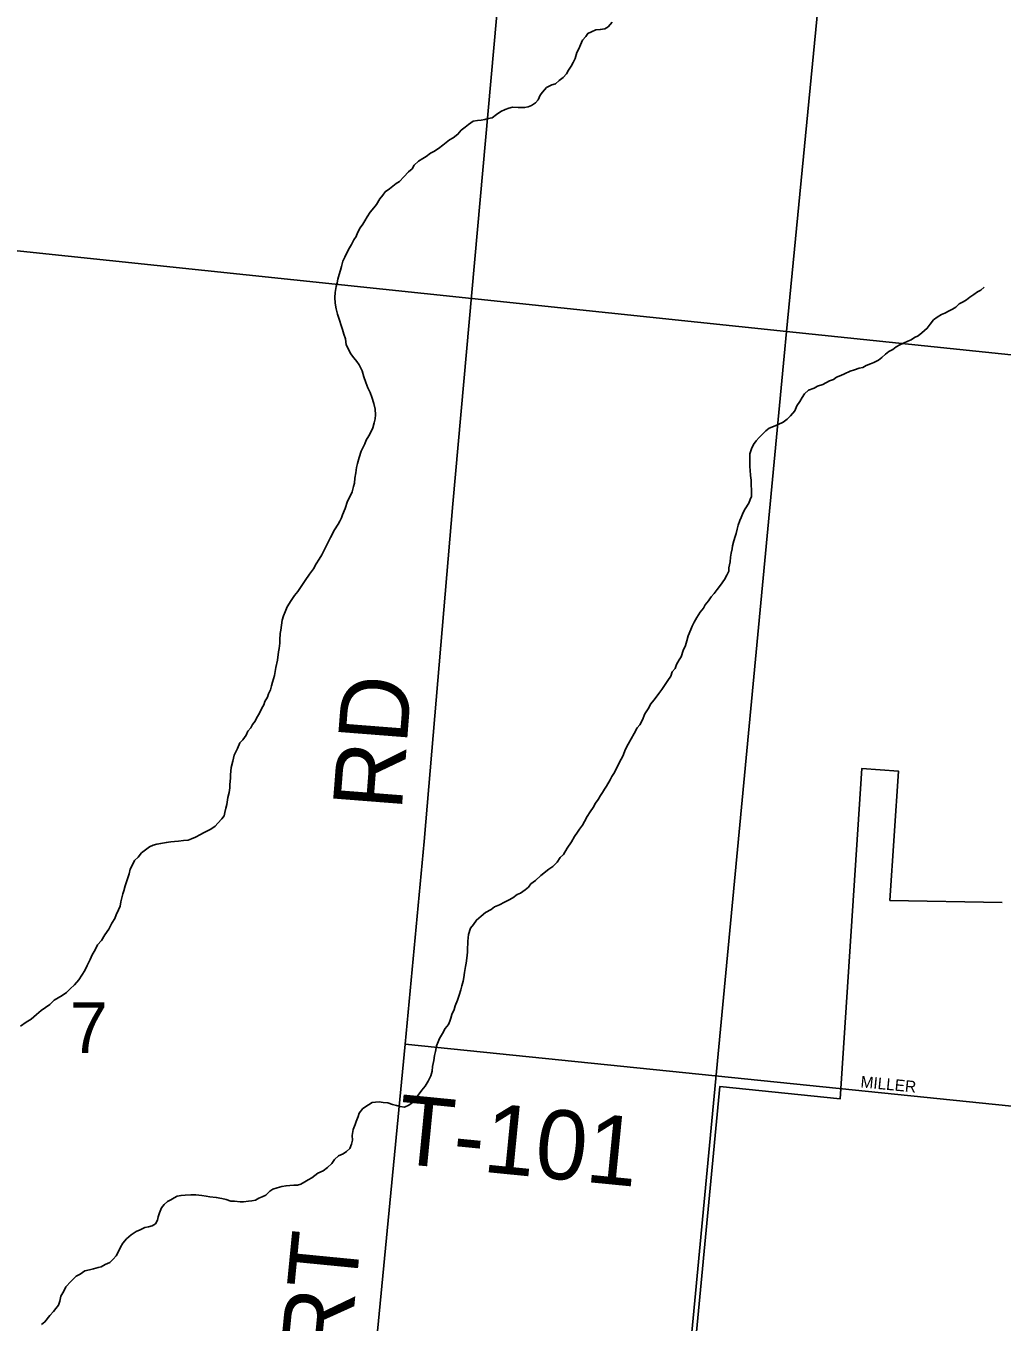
# Model space of a CAD drawing. Extents: x 1310247 to 1664935, y 284496 to 704931.
# Drawn here: x 1478998 to 1483233, y 534778 to 540403 of the extents above; entities that cross this region are included whole.
import ezdxf

# ---------------------------------------------------------------- set-up
doc = ezdxf.new("R2010")
doc.units = 0
for name, color, linetype in [('GM_X_Corporation_Text', 7, 'Continuous'), ('GM_X_County', 7, 'Continuous'), ('GM_X_County_Road_Text', 7, 'Continuous'), ('GM_X_County_Subdivision_Text', 7, 'Continuous'), ('GM_X_Major_Lake_Text', 7, 'Continuous'), ('GM_X_Minor_River_Text', 7, 'Continuous'), ('GM_X_Rail_Line', 7, 'Continuous'), ('GM_X_Township_Road', 7, 'Continuous'), ('GM_X_Township_Subdivision', 7, 'Continuous'), ('GM_X_US_Location', 7, 'Continuous')]:
    doc.layers.add(name, color=color, linetype=linetype)

msp = doc.modelspace()

# ---------------------------------------------------------------- linework, layer by layer
at = {"layer": 'GM_X_Corporation_Text'}
msp.add_lwpolyline([(1482526.6, 535791.8), (1484192.7, 535621.9), (1484200.6, 535621.1)], dxfattribs=at)
at = {"layer": 'GM_X_County'}
for points in [[(1482824.4, 544500.5), (1482296.8, 539077.3), (1476836.6, 539649.6), (1477436.1, 545815.4)], [(1488278.4, 543814.4), (1487769.1, 538508.9), (1482296.8, 539077.3), (1482824.4, 544500.5)], [(1482296.8, 539077.3), (1481688, 532623.9), (1476536.2, 533008.3), (1476252.8, 533037.6), (1476836.6, 539649.6)], [(1487769.1, 538508.9), (1487146.6, 532073.7), (1481965.4, 532596.7), (1481688, 532623.9), (1482296.8, 539077.3)]]:
    msp.add_lwpolyline(points, close=True, dxfattribs=at)
at = {"layer": 'GM_X_County_Road_Text'}
msp.add_lwpolyline([(1481149, 532772.8), (1481084.4, 532843.1), (1480900.4, 533069.7), (1480812.9, 533208.1), (1480562.1, 533693.1), (1480490.5, 533821.1), (1480457.7, 533888), (1480449.5, 533974.5), (1480643.3, 535983.8), (1480726.5, 536863.2), (1480850.5, 538329.9), (1481180.6, 542015), (1481216.3, 542748.8), (1481232.1, 543112), (1481249.6, 543457.3), (1481303, 544311.9), (1481316.9, 544534.5), (1481345.5, 544835.1)], dxfattribs=at)
at = {"layer": 'GM_X_County_Subdivision_Text'}
msp.add_lwpolyline([(1480643.3, 535983.8), (1482526.6, 535791.8)], dxfattribs=at)
at = {"layer": 'GM_X_Major_Lake_Text'}
msp.add_lwpolyline([(1483665.3, 533123.9), (1482695.3, 533200.4), (1481767.3, 533260.9), (1482008, 535800.7), (1482530.4, 535747.7), (1482624.4, 537180.8), (1482782.6, 537169.7), (1482746.2, 536608.1), (1483233.2, 536598.6)], dxfattribs=at)
at = {"layer": 'GM_X_Minor_River_Text'}
for points in [[(1481092.9, 540046.5), (1481109.1, 540050.1), (1481133.2, 540049.3), (1481147.2, 540048.9), (1481161.3, 540048.4), (1481177.4, 540052), (1481191.7, 540057.5), (1481208.2, 540069), (1481220.7, 540082.7), (1481229.3, 540102.4), (1481239.8, 540116.1), (1481256.6, 540135.7), (1481279, 540147), (1481295.3, 540152.5), (1481311.8, 540166), (1481328.3, 540179.5), (1481342.9, 540195.1), (1481351.5, 540210.9), (1481364.1, 540228.5), (1481372.7, 540244.3), (1481381.3, 540262), (1481388.2, 540287.9), (1481396.7, 540303.6), (1481403.4, 540321.4), (1481412, 540341.2), (1481426.6, 540356.8), (1481435.1, 540370.6), (1481451.4, 540378.1), (1481469.8, 540385.5), (1481489.9, 540386.9), (1481510.1, 540390.3), (1481524.5, 540399.8), (1481541.2, 540419.4)], [(1480382.5, 538309.5), (1480393.6, 538341.2), (1480406.4, 538364.8), (1480413, 538380.7), (1480419.8, 538404.5), (1480424.3, 538418.4), (1480425, 538440.4), (1480429.8, 538464.3), (1480432.5, 538486.2), (1480437.1, 538504.1), (1480444, 538530), (1480453, 538557.7), (1480461.6, 538575.5), (1480468.1, 538589.3), (1480474.6, 538605.2), (1480485.3, 538624.9), (1480496, 538642.6), (1480502.5, 538658.4), (1480509.3, 538680.2), (1480513.9, 538698.1), (1480514.5, 538716.1), (1480513.3, 538740.2), (1480508, 538764.4), (1480498.9, 538792.7), (1480491.5, 538813), (1480482.2, 538833.3), (1480472.9, 538855.6), (1480463.6, 538880), (1480456.5, 538906.2), (1480443.3, 538932.7), (1480433.7, 538947), (1480420.2, 538963.4), (1480406.7, 538981.9), (1480399.2, 538998.2), (1480387.8, 539018.5), (1480384.7, 539044.7), (1480377.3, 539064.9), (1480371.9, 539085.1), (1480366.5, 539103.3), (1480359.2, 539125.6), (1480350, 539151.9), (1480344.8, 539176.1), (1480339.6, 539200.3), (1480338.4, 539224.4), (1480339.1, 539246.4), (1480344, 539272.3), (1480348.5, 539288.2), (1480351, 539304.2), (1480357.7, 539324), (1480362.4, 539343.9), (1480366.9, 539359.8), (1480373.7, 539381.6), (1480382.3, 539399.4), (1480391, 539419.1), (1480401.8, 539440.8), (1480410.3, 539454.6), (1480421, 539474.3), (1480431.5, 539490), (1480436.1, 539505.9), (1480448.8, 539527.5), (1480459.4, 539543.2), (1480467.9, 539557), (1480478.5, 539574.7), (1480491.2, 539594.3), (1480507.9, 539613.8), (1480518.4, 539627.5), (1480533.4, 539653.1), (1480545.9, 539668.8), (1480556.4, 539682.5), (1480575, 539695.9), (1480589.4, 539707.5), (1480603.8, 539719.1), (1480618.2, 539728.7), (1480637, 539748.1), (1480657.8, 539769.5), (1480674.3, 539783), (1480682.8, 539798.8), (1480701.5, 539816.2), (1480720, 539827.7), (1480734.3, 539837.2), (1480752.9, 539850.7), (1480767.2, 539858.3), (1480787.7, 539871.7), (1480806.2, 539885.1), (1480820.7, 539896.7), (1480835.1, 539908.3), (1480851.5, 539917.8), (1480872.1, 539933.2), (1480886.8, 539950.8), (1480903.3, 539964.2), (1480917.7, 539975.8), (1480938.3, 539989.2), (1480956.5, 539992.7), (1480972.6, 539994.2), (1480988.8, 539997.7), (1481003, 540001.2), (1481021.2, 540004.7), (1481039.7, 540018.2), (1481058.2, 540031.6), (1481076.6, 540041), (1481092.9, 540046.5)], [(1481897.3, 537815.9), (1481908, 537835.7), (1481922.9, 537859.2), (1481937.5, 537876.8), (1481944, 537890.7), (1481958.6, 537908.2), (1481971.3, 537925.9), (1481983.8, 537939.5), (1481996.4, 537957.1), (1482011.1, 537976.7), (1482028, 538000.2), (1482038.7, 538019.9), (1482047.3, 538037.7), (1482047.8, 538051.7), (1482052.6, 538077.6), (1482055.3, 538097.6), (1482057.9, 538115.5), (1482062.5, 538133.4), (1482063, 538147.4), (1482069.7, 538169.2), (1482074.3, 538187.1), (1482078.8, 538201), (1482083.4, 538218.9), (1482088, 538236.8), (1482094.7, 538256.6), (1482101.2, 538270.4), (1482110, 538292.2), (1482118.5, 538308), (1482133.4, 538331.6), (1482139.9, 538347.4), (1482146.4, 538361.2), (1482145.4, 538393.3), (1482143.9, 538407.4), (1482144.7, 538431.4), (1482141.3, 538451.5), (1482140.1, 538475.6), (1482138.6, 538489.7), (1482139.1, 538505.7), (1482137.8, 538527.8), (1482138.4, 538545.8), (1482145.2, 538567.6), (1482153.9, 538587.4), (1482166.4, 538603), (1482178.9, 538616.7), (1482191.4, 538630.3), (1482208, 538645.8), (1482222.5, 538657.4), (1482240.8, 538664.8), (1482261.2, 538674.2), (1482283.6, 538683.5), (1482300.1, 538697), (1482314.7, 538710.6), (1482333.4, 538732.1), (1482342.2, 538753.8), (1482354.9, 538773.5), (1482365.5, 538791.2), (1482376.1, 538806.9), (1482392.7, 538822.4), (1482417.1, 538831.7), (1482431.4, 538839.2), (1482455.8, 538846.5), (1482484.5, 538863.7), (1482500.7, 538869.2), (1482515.1, 538878.7), (1482533.4, 538886.2), (1482549.8, 538893.7), (1482574.2, 538905), (1482592.5, 538910.4), (1482612.8, 538917.8), (1482629, 538921.3), (1482643.3, 538928.9), (1482661.7, 538936.3), (1482675.9, 538941.9), (1482696.4, 538953.3), (1482710.8, 538964.8), (1482727.4, 538978.4), (1482741.8, 538989.9), (1482758.2, 538999.4), (1482772.6, 539011), (1482789, 539018.5), (1482805.3, 539026), (1482823.7, 539035.5), (1482837.9, 539041.1), (1482852.3, 539050.6), (1482868.6, 539058.2), (1482885.2, 539071.7), (1482907.9, 539091), (1482920.5, 539108.6), (1482935.3, 539128.2), (1482951.7, 539139.7), (1482970.2, 539151.2), (1482984.4, 539156.8), (1483002.8, 539166.2), (1483017.1, 539173.8), (1483031.5, 539183.3), (1483046, 539196.9), (1483064.4, 539206.4), (1483078.7, 539213.9), (1483093.2, 539225.5), (1483109.6, 539237), (1483126.1, 539248.5)], [(1483126.1, 539248.5), (1483140.4, 539256.1), (1483154.9, 539269.7)], [(1479357.8, 536483.9), (1479370.7, 536509.6), (1479383.4, 536529.2), (1479389.9, 536545), (1479400.7, 536566.7), (1479407.2, 536582.6), (1479409.9, 536602.5), (1479419.1, 536636.3), (1479423.5, 536650.2), (1479428.3, 536672.1), (1479437.2, 536697.8), (1479446.1, 536723.6), (1479450.7, 536743.5), (1479461.5, 536765.2), (1479470.1, 536781), (1479484.6, 536796.5), (1479499.3, 536814.1), (1479517.8, 536827.6), (1479534.3, 536841.1), (1479550.6, 536848.6), (1479566.8, 536852.1), (1479583, 536855.6), (1479607.2, 536858.9), (1479627.5, 536862.3), (1479643.6, 536863.8), (1479659.7, 536865.3), (1479681.9, 536868.6), (1479702.1, 536870), (1479716.3, 536875.5), (1479734.6, 536883), (1479755.1, 536894.4), (1479769.4, 536901.9), (1479785.7, 536909.5), (1479800.1, 536917), (1479818.6, 536930.5), (1479831.1, 536944.1), (1479847.7, 536961.7), (1479858.2, 536975.3), (1479860.7, 536989.3), (1479865.4, 537009.2), (1479869.9, 537025.1), (1479874.9, 537055), (1479879.7, 537076.9), (1479882.3, 537096.8), (1479882.8, 537110.8), (1479885.7, 537138.8), (1479886.2, 537152.8), (1479889.3, 537184.8), (1479896.2, 537212.6), (1479901.1, 537238.5), (1479916.1, 537268.1), (1479926.9, 537291.8), (1479939.5, 537305.4), (1479954.2, 537325), (1479960.8, 537342.8), (1479973.3, 537356.5), (1479981.8, 537372.2), (1479992.3, 537385.9), (1479998.8, 537399.8), (1480011.6, 537421.4), (1480022.4, 537443.1), (1480030.9, 537456.9), (1480035.3, 537470.8), (1480046, 537490.4), (1480050.5, 537504.3), (1480059.1, 537522.1), (1480063.7, 537540), (1480068.3, 537555.9), (1480077.2, 537583.7), (1480082.4, 537619.6), (1480089.5, 537651.4), (1480094.7, 537687.3), (1480097.2, 537701.2), (1480100, 537725.2), (1480100.5, 537739.2), (1480101.4, 537767.2), (1480103.8, 537781.2), (1480106.6, 537803.1), (1480109.3, 537825.1), (1480115.9, 537842.9), (1480122.5, 537860.7), (1480131.3, 537882.5), (1480148.3, 537910), (1480163.1, 537931.6), (1480177.7, 537949.2), (1480194.6, 537974.7), (1480209.4, 537996.3), (1480228.4, 538023.8), (1480245.2, 538047.3), (1480258, 538068.9), (1480270.7, 538088.6), (1480281.4, 538108.3), (1480294.3, 538133.9), (1480305, 538153.6), (1480320.1, 538183.2), (1480337.2, 538216.7), (1480352.1, 538240.3), (1480360.6, 538254.1), (1480367.1, 538267.9), (1480371.5, 538281.8), (1480382.5, 538309.5)], [(1480774.9, 535953.3), (1480779.7, 535977.2), (1480786.4, 535995), (1480792.8, 536008.8), (1480805.6, 536030.5), (1480816.4, 536052.2), (1480831, 536069.8), (1480837.5, 536083.6), (1480842, 536097.5), (1480846.5, 536113.4), (1480855.3, 536135.1), (1480859.8, 536151), (1480870.7, 536174.7), (1480877.4, 536196.6), (1480884.2, 536220.4), (1480888.8, 536238.3), (1480895.5, 536258.1), (1480898, 536274), (1480900.8, 536296), (1480905.6, 536321.9), (1480908.1, 536335.8), (1480910.9, 536357.8), (1480913.7, 536383.8), (1480914.4, 536403.8), (1480914.8, 536417.8), (1480915.3, 536431.8), (1480918.2, 536459.8), (1480927.2, 536487.5), (1480939.8, 536503.2), (1480952.5, 536522.8), (1480973.1, 536540.2), (1480991.7, 536555.7), (1481016.3, 536568.9), (1481030.7, 536580.5), (1481053.1, 536589.8), (1481073.6, 536601.2), (1481091.9, 536608.7), (1481110.4, 536620.1), (1481128.9, 536633.6), (1481143.2, 536639.2), (1481163.8, 536654.5), (1481178.2, 536666.1), (1481188.7, 536679.8), (1481209.3, 536695.2), (1481232.1, 536716.5), (1481267.2, 536743.5), (1481283.6, 536755), (1481302.4, 536774.5), (1481315.1, 536794.1), (1481329.6, 536807.7), (1481346.6, 536835.2), (1481365.5, 536862.7), (1481378.4, 536886.3), (1481391, 536904), (1481399.5, 536917.7), (1481412.1, 536935.4), (1481420.7, 536951.1), (1481433.5, 536972.8), (1481446.2, 536992.4), (1481458.9, 537012.1), (1481469.5, 537029.8), (1481480.1, 537045.5), (1481490.7, 537063.2), (1481499.2, 537076.9), (1481507.7, 537090.7), (1481516.2, 537104.5), (1481533.2, 537132), (1481539.7, 537145.8), (1481548.1, 537159.6), (1481561, 537183.2), (1481571.7, 537204.9), (1481588.9, 537236.4), (1481597.7, 537262.2), (1481610.6, 537285.9), (1481623.4, 537309.5), (1481636.3, 537333.2), (1481649.1, 537356.8), (1481661.6, 537370.4), (1481672.4, 537392.1), (1481683.3, 537417.9), (1481698, 537439.4), (1481708.8, 537461.2), (1481721.4, 537476.8), (1481731.9, 537490.5), (1481744.4, 537506.1), (1481757.1, 537523.8), (1481767.7, 537541.5), (1481782.5, 537563), (1481795.1, 537580.7), (1481801.8, 537600.5), (1481814.3, 537614.2), (1481820.9, 537632), (1481831.6, 537651.7), (1481840.1, 537665.4), (1481849.1, 537693.2), (1481859.8, 537714.9), (1481864.5, 537734.8), (1481871.2, 537756.7), (1481882.2, 537784.4), (1481888.7, 537798.2), (1481897.3, 537815.9)], [(1478974.2, 536063), (1478998.9, 536080.2), (1479021.4, 536093.6), (1479044.1, 536112.9), (1479064.8, 536130.3), (1479083.3, 536143.8), (1479101.9, 536157.2), (1479120.5, 536174.7), (1479139, 536186.1), (1479155.4, 536195.6), (1479173.9, 536209.1), (1479190.5, 536224.6), (1479209.1, 536242.1), (1479227.9, 536263.5), (1479240.6, 536283.2), (1479253.4, 536304.8), (1479264.2, 536326.5), (1479277.1, 536352.2), (1479285.8, 536371.9), (1479298.5, 536393.6), (1479309.3, 536415.3), (1479326, 536434.8), (1479340.9, 536458.4), (1479357.8, 536483.9)], [(1479274.9, 535005.8), (1479291.1, 535009.3), (1479311.3, 535014.7), (1479325.5, 535018.3), (1479341.9, 535027.8), (1479362.3, 535037.2), (1479376.8, 535050.8), (1479389.4, 535066.4), (1479402.2, 535090), (1479408.7, 535103.9), (1479419.3, 535121.6), (1479434, 535139.2), (1479454.7, 535156.5), (1479477.3, 535171.9), (1479493.6, 535179.4), (1479514, 535188.8), (1479530.2, 535192.3), (1479546.4, 535195.8), (1479560.8, 535205.4), (1479569.3, 535221.1), (1479571.8, 535235.1), (1479578.4, 535252.9), (1479587.1, 535274.7), (1479597.6, 535288.4), (1479612.2, 535302), (1479626.5, 535309.5), (1479640.8, 535317.1), (1479655.1, 535324.7), (1479671.3, 535328.2), (1479689.4, 535329.6), (1479713.6, 535330.9), (1479735.7, 535330.2), (1479761.7, 535327.4), (1479779.7, 535324.8), (1479795.7, 535322.3), (1479823.7, 535319.5), (1479847.7, 535314.7), (1479867.6, 535310.1), (1479887.5, 535303.5), (1479903.5, 535303), (1479927.6, 535300.2), (1479941.6, 535299.8), (1479963.8, 535303.1), (1479978, 535304.7), (1479994.1, 535308.2), (1480008.5, 535315.8), (1480022.7, 535321.3), (1480039, 535328.8), (1480055.7, 535346.4), (1480070.1, 535355.9), (1480088.3, 535361.4), (1480108.6, 535366.8), (1480126.8, 535370.2), (1480142.9, 535371.7), (1480161, 535373.2), (1480177.1, 535372.7), (1480191.3, 535376.2), (1480207.7, 535387.7), (1480222.1, 535395.3), (1480238.4, 535404.8), (1480265.2, 535424), (1480287.7, 535435.4), (1480306.2, 535448.8), (1480324.9, 535466.3), (1480337.5, 535483.9), (1480354.1, 535499.4), (1480374.5, 535508.8), (1480388.9, 535518.4), (1480403.4, 535532), (1480410, 535549.8), (1480414.6, 535567.7), (1480413.3, 535587.8), (1480418.1, 535613.7), (1480426.9, 535635.4), (1480431.4, 535649.3), (1480440.1, 535671.1), (1480444.6, 535685), (1480459.3, 535704.6), (1480484, 535721.8), (1480500.4, 535731.3), (1480514.5, 535732.9), (1480530.6, 535734.4), (1480548.6, 535731.9), (1480568.6, 535729.2), (1480588.5, 535722.6), (1480606.4, 535718), (1480622.4, 535713.5), (1480640.4, 535711), (1480658.8, 535720.4), (1480673.1, 535730), (1480687.7, 535745.6), (1480700.4, 535763.2), (1480715.1, 535784.8), (1480729.8, 535802.4), (1480742.5, 535824), (1480755.4, 535847.7), (1480760.1, 535867.6), (1480762.7, 535887.5), (1480767.6, 535913.4), (1480770.3, 535935.4), (1480774.9, 535953.3)], [(1479066.1, 534767.8), (1479080.5, 534779.4), (1479101.5, 534806.8), (1479118.2, 534824.3), (1479128.7, 534838), (1479139.2, 534851.7), (1479145.8, 534869.5), (1479150.5, 534891.4), (1479163.3, 534913.1), (1479171.9, 534930.8), (1479192.8, 534954.2), (1479215.7, 534977.6), (1479234.1, 534987), (1479254.6, 535000.4), (1479274.9, 535005.8)]]:
    msp.add_lwpolyline(points, dxfattribs=at)

# ---------------------------------------------------------------- texts
at = {"layer": 'GM_X_Rail_Line'}
msp.add_text('MILLER', height=50, rotation=354.5067, dxfattribs=at).set_placement((1482617, 535797.2))
at = {"layer": 'GM_X_Township_Road'}
for s, rotation, p in [('RD', 85.5257, (1480627.9, 536994.2)), ('HART', 84.4157, (1480346.5, 534066))]:
    msp.add_text(s, height=300, rotation=rotation, dxfattribs=at).set_placement(p)
at = {"layer": 'GM_X_Township_Subdivision'}
msp.add_text('T-101', height=300, rotation=354.3731, dxfattribs=at).set_placement((1480598.4, 535468.3))
at = {"layer": 'GM_X_US_Location'}
msp.add_text('7', height=221, rotation=0, dxfattribs=at).set_placement((1479188.6, 535945.6))

doc.saveas('drawing.dxf')
